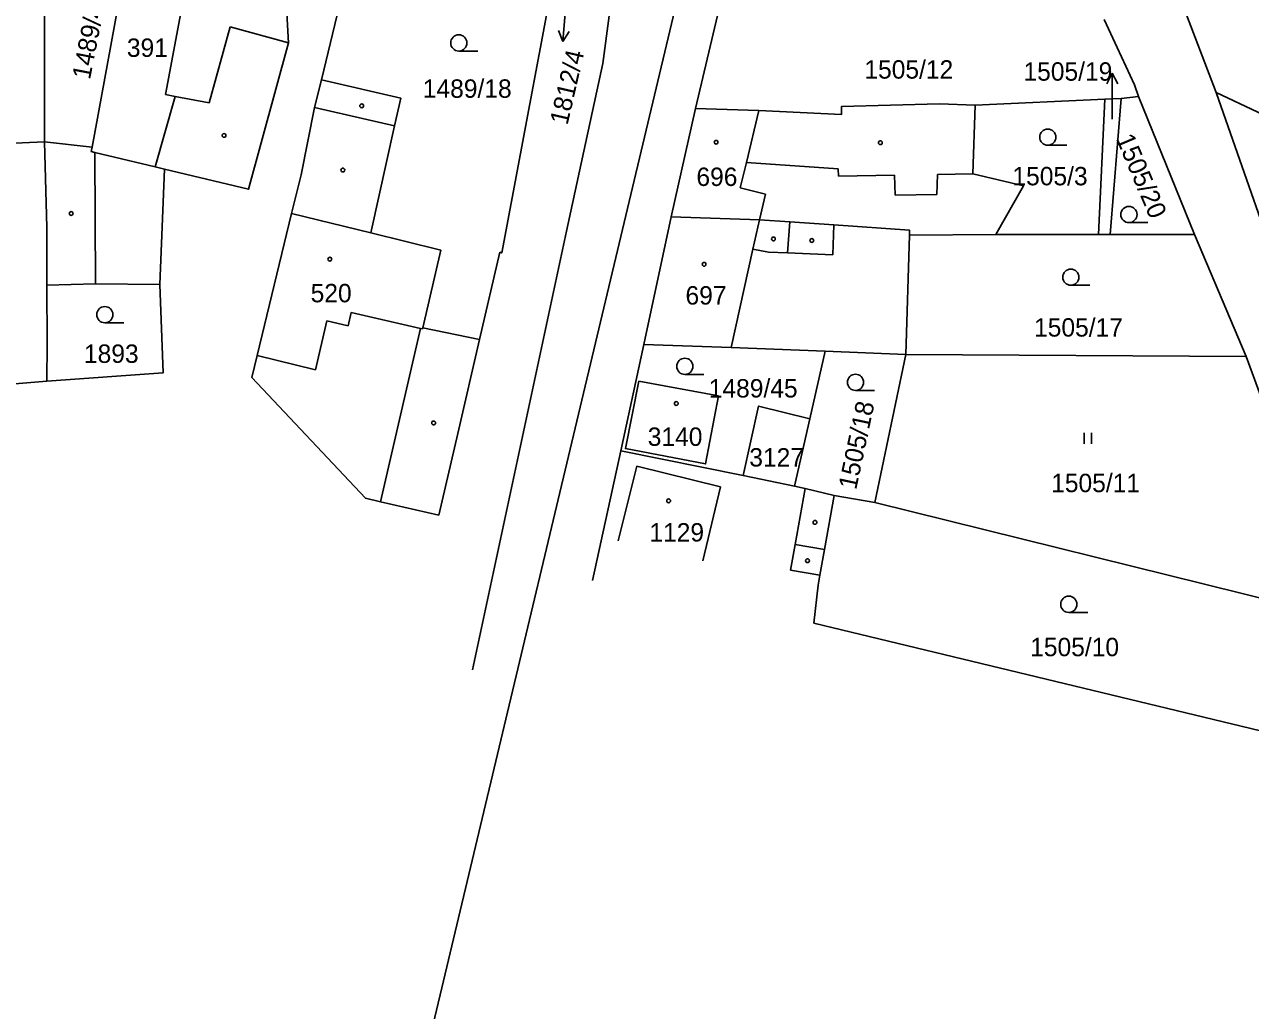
# Model space of a CAD drawing. Extents: x -779330 to -774454, y -1144748 to -1142831.
# Drawn here: x -777374.1 to -777260.7, y -1144037.5 to -1143946.4 of the extents above; entities that cross this region are included whole.
import ezdxf

# ---------------------------------------------------------------- set-up
doc = ezdxf.new("R2010")
doc.units = 0
for name, color, linetype in [('Hranice parcel', 7, 'Continuous'), ('Parcelní čísla', 7, 'Continuous'), ('Pop  PČ popisy', 7, 'Continuous'), ('Vnitřní kresba', 7, 'Continuous'), ('Značky budov', 7, 'Continuous'), ('Značky kultur', 7, 'Continuous')]:
    doc.layers.add(name, color=color, linetype=linetype)

msp = doc.modelspace()

# ---------------------------------------------------------------- linework, layer by layer
at = {"layer": 'Hranice parcel'}
for p, q in [((-777372.24, -1143957.25), (-777372.2, -1143931.77)), ((-777346.63, -1143951.52), (-777343.75, -1143939.71)), ((-777312.04, -1143954.18), (-777309.73, -1143944.43)), ((-777266.65, -1143945.51), (-777263.88, -1143952.69)), ((-777274.18, -1143953.33), (-777286.17, -1143953.86)), ((-777274.76, -1143965.81), (-777274.18, -1143953.33)), ((-777274.18, -1143953.33), (-777272.69, -1143953.26)), ((-777273.69, -1143965.81), (-777272.69, -1143953.26)), ((-777272.69, -1143953.26), (-777271.08, -1143953.07)), ((-777265.9, -1143965.83), (-777271.08, -1143953.07)), ((-777263.88, -1143952.69), (-777258.48, -1143968.19)), ((-777312.04, -1143954.18), (-777314.28, -1143964.19)), ((-777314.28, -1143964.19), (-777316.81, -1143975.99)), ((-777292.6, -1143976.92), (-777292.26, -1143965.88)), ((-777292.26, -1143965.88), (-777284.26, -1143965.84)), ((-777284.26, -1143965.84), (-777274.76, -1143965.81)), ((-777273.69, -1143965.81), (-777274.76, -1143965.81)), ((-777265.9, -1143965.83), (-777273.69, -1143965.81)), ((-777261.12, -1143977.11), (-777265.9, -1143965.83)), ((-777318.94, -1143985.81), (-777316.81, -1143975.99)), ((-777301.46, -1143982.86), (-777300.05, -1143976.62)), ((-777300.05, -1143976.62), (-777292.6, -1143976.92)), ((-777292.6, -1143976.92), (-777295.44, -1143990.58)), ((-777261.12, -1143977.11), (-777292.6, -1143976.92)), ((-777252.26, -1144001.3), (-777261.12, -1143977.11)), ((-777301.46, -1143982.86), (-777302.87, -1143989.08)), ((-777318.94, -1143985.81), (-777321.57, -1143997.81)), ((-777307.63, -1143988.11), (-777318.94, -1143985.81)), ((-777302.87, -1143989.08), (-777307.63, -1143988.11)), ((-777295.44, -1143990.58), (-777299.22, -1143989.94)), ((-777252.26, -1144001.3), (-777295.44, -1143990.58)), ((-777301.08, -1144001.76), (-777246.41, -1144014.94))]:
    msp.add_line(p, q, dxfattribs=at)
for points in [[(-777294.6, -1143849.93), (-777307.3, -1143865.67), (-777309.05, -1143868.8), (-777311.09, -1143883.18), (-777313.96, -1143945.06), (-777339.24, -1144051.23), (-777343.7, -1144063.85), (-777354.92, -1144095.57), (-777359.4, -1144105.13), (-777377.33, -1144140.81), (-777384.39, -1144152.73), (-777399.7, -1144183.35)], [(-777332.65, -1144006.07), (-777323.96, -1143965.53), (-777320.6, -1143950.03), (-777317.86, -1143929.35), (-777317.3, -1143892.87), (-777317.93, -1143883.67), (-777320.94, -1143881.7)], [(-777363.4, -1143933.71), (-777367.83, -1143957.76), (-777372.24, -1143957.25)], [(-777361.57, -1143970.44), (-777361.14, -1143959.78), (-777353.37, -1143961.64), (-777349.67, -1143948.11), (-777350.18, -1143938.72), (-777350.82, -1143936.44), (-777357.51, -1143934.99), (-777363.4, -1143933.71)], [(-777325.64, -1143944.56), (-777329.95, -1143967.52), (-777330.12, -1143967.47), (-777332.01, -1143975.52)], [(-777271.08, -1143953.07), (-777271.45, -1143951.98), (-777274.26, -1143945.97)], [(-777346.63, -1143951.52), (-777347.26, -1143954.09), (-777348.51, -1143960.32), (-777349.38, -1143963.89), (-777352.57, -1143977.01), (-777353.07, -1143979.04), (-777342.56, -1143990.2), (-777341.15, -1143990.53), (-777335.78, -1143991.75), (-777334.01, -1143984.21), (-777332.01, -1143975.52)], [(-777332.01, -1143975.52), (-777337.26, -1143974.45), (-777335.59, -1143967.26), (-777342.05, -1143965.68), (-777339.86, -1143955.79), (-777339.29, -1143953.22), (-777346.63, -1143951.52)], [(-777171.18, -1143997.24), (-777214.44, -1143976.01), (-777263.88, -1143952.69)], [(-777286.17, -1143953.86), (-777289.46, -1143953.75), (-777298.53, -1143953.99), (-777298.52, -1143954.72), (-777306.18, -1143954.38), (-777312.04, -1143954.18)], [(-777284.26, -1143965.84), (-777281.7, -1143961.34), (-777286.39, -1143960.23), (-777286.17, -1143953.86)], [(-777402.5, -1143958.01), (-777402.7, -1143965.53), (-777403.13, -1143981.77), (-777401.59, -1143981.77), (-777398.88, -1143981.65), (-777389.09, -1143980.8), (-777372.01, -1143979.38)], [(-777372.24, -1143957.25), (-777376.4, -1143957.46), (-777387.4, -1143958.06), (-777396.94, -1143957.77), (-777396.94, -1143958.12), (-777402.5, -1143958.01)], [(-777372.01, -1143970.52), (-777372, -1143965.18), (-777372.24, -1143957.25)], [(-777314.28, -1143964.19), (-777306.13, -1143964.46), (-777303.32, -1143964.66), (-777299.23, -1143964.94), (-777292.24, -1143965.43), (-777292.26, -1143965.88)], [(-777372.01, -1143970.52), (-777367.5, -1143970.39), (-777361.57, -1143970.44)], [(-777361.57, -1143970.44), (-777361.25, -1143978.6), (-777372.01, -1143979.38)], [(-777372.01, -1143979.38), (-777371.98, -1143975.94), (-777372.01, -1143970.52)], [(-777316.81, -1143975.99), (-777308.74, -1143976.27), (-777300.05, -1143976.62)], [(-777317.28, -1143979.37), (-777309.91, -1143980.75), (-777311.11, -1143987.03), (-777318.52, -1143985.61), (-777317.28, -1143979.37)], [(-777307.63, -1143988.11), (-777306.2, -1143981.69), (-777301.46, -1143982.86)], [(-777299.22, -1143989.94), (-777301.9, -1143989.31), (-777302.87, -1143989.08)], [(-777301.08, -1144001.76), (-777300.69, -1143998.22), (-777300.53, -1143997.32), (-777300.11, -1143994.95), (-777299.22, -1143989.94)]]:
    msp.add_lwpolyline(points, dxfattribs=at)
at = {"layer": 'Pop  PČ popisy'}
for p, q in [((-777324.04, -1143945.01), (-777324.3, -1143948)), ((-777324.3, -1143948), (-777324.71, -1143946.96)), ((-777324.3, -1143948), (-777323.71, -1143947.05)), ((-777273.5, -1143950.91), (-777274, -1143951.91)), ((-777273.5, -1143953.91), (-777273.5, -1143950.91)), ((-777273.5, -1143950.91), (-777273, -1143951.91)), ((-777273.5, -1143955.17), (-777273.5, -1143953.91))]:
    msp.add_line(p, q, dxfattribs=at)
at = {"layer": 'Vnitřní kresba'}
for p, q in [((-777361.03, -1143952.89), (-777358.8, -1143940.92)), ((-777355.07, -1143946.63), (-777357, -1143953.67)), ((-777355.07, -1143946.63), (-777349.67, -1143948.11)), ((-777360.15, -1143953.06), (-777361.99, -1143959.57)), ((-777361.03, -1143952.89), (-777360.15, -1143953.06)), ((-777360.15, -1143953.06), (-777357, -1143953.67)), ((-777347.26, -1143954.09), (-777339.86, -1143955.79)), ((-777307.32, -1143959.16), (-777306.18, -1143954.38)), ((-777367.83, -1143957.76), (-777367.9, -1143958.16)), ((-777367.9, -1143958.16), (-777367.56, -1143958.24)), ((-777367.56, -1143958.24), (-777361.99, -1143959.57)), ((-777367.5, -1143970.39), (-777367.56, -1143958.24)), ((-777307.9, -1143961.52), (-777307.32, -1143959.16)), ((-777307.32, -1143959.16), (-777298.83, -1143959.77)), ((-777361.99, -1143959.57), (-777361.14, -1143959.78)), ((-777298.83, -1143959.77), (-777298.81, -1143960.42)), ((-777298.81, -1143960.42), (-777293.64, -1143960.34)), ((-777293.64, -1143960.34), (-777293.58, -1143962.2)), ((-777289.73, -1143962.14), (-777289.65, -1143960.28)), ((-777289.65, -1143960.28), (-777286.39, -1143960.23)), ((-777305.55, -1143962.1), (-777307.9, -1143961.52)), ((-777306.13, -1143964.46), (-777305.55, -1143962.1)), ((-777293.58, -1143962.2), (-777289.73, -1143962.14)), ((-777349.38, -1143963.89), (-777342.05, -1143965.68)), ((-777306.74, -1143967.19), (-777306.13, -1143964.46)), ((-777303.32, -1143964.66), (-777303.54, -1143967.53)), ((-777299.34, -1143967.71), (-777299.23, -1143964.94)), ((-777308.74, -1143976.27), (-777306.74, -1143967.19)), ((-777306.74, -1143967.19), (-777305.28, -1143967.45)), ((-777305.28, -1143967.45), (-777303.54, -1143967.53)), ((-777303.54, -1143967.53), (-777299.34, -1143967.71)), ((-777347.17, -1143978.33), (-777346.12, -1143973.8)), ((-777346.12, -1143973.8), (-777344.16, -1143974.26)), ((-777344.16, -1143974.26), (-777343.87, -1143973.02)), ((-777343.87, -1143973.02), (-777337.46, -1143974.51)), ((-777341.15, -1143990.53), (-777337.46, -1143974.51)), ((-777337.46, -1143974.51), (-777337.28, -1143974.55)), ((-777337.28, -1143974.55), (-777337.26, -1143974.45)), ((-777352.57, -1143977.01), (-777347.17, -1143978.33)), ((-777319.18, -1143994.13), (-777317.45, -1143987.24)), ((-777317.45, -1143987.24), (-777309.72, -1143989.14)), ((-777309.72, -1143989.14), (-777311.35, -1143995.99)), ((-777301.9, -1143989.31), (-777302.83, -1143994.47)), ((-777303.25, -1143996.84), (-777302.83, -1143994.47)), ((-777302.83, -1143994.47), (-777300.11, -1143994.95)), ((-777300.53, -1143997.32), (-777303.25, -1143996.84))]:
    msp.add_line(p, q, dxfattribs=at)
at = {"layer": 'Značky budov'}
for centre in [(-777342.9, -1143953.93), (-777355.63, -1143956.67), (-777310.13, -1143957.3), (-777294.94, -1143957.34), (-777344.64, -1143959.87), (-777369.76, -1143963.88), (-777304.83, -1143966.24), (-777301.28, -1143966.38), (-777345.84, -1143968.1), (-777311.24, -1143968.58), (-777313.81, -1143981.44), (-777336.25, -1143983.24), (-777314.52, -1143990.44), (-777300.99, -1143992.43), (-777301.68, -1143995.97)]:
    msp.add_circle(centre, 0.175, dxfattribs=at)
at = {"layer": 'Značky kultur'}
for p, q in [((-777333.92, -1143948.87), (-777332.17, -1143948.87)), ((-777279.46, -1143957.58), (-777277.71, -1143957.58)), ((-777271.96, -1143964.73), (-777270.21, -1143964.73)), ((-777277.33, -1143970.52), (-777275.58, -1143970.52)), ((-777366.65, -1143973.98), (-777364.9, -1143973.98)), ((-777313.02, -1143978.76), (-777311.27, -1143978.76)), ((-777297.24, -1143980.24), (-777295.49, -1143980.24)), ((-777276.1, -1143985.16), (-777276.1, -1143984.16)), ((-777275.43, -1143985.16), (-777275.43, -1143984.16)), ((-777277.52, -1144000.75), (-777275.77, -1144000.75))]:
    msp.add_line(p, q, dxfattribs=at)
for centre in [(-777333.92, -1143948.12), (-777279.46, -1143956.83), (-777271.96, -1143963.98), (-777277.33, -1143969.77), (-777366.65, -1143973.23), (-777313.02, -1143978.01), (-777297.24, -1143979.49), (-777277.52, -1144000)]:
    msp.add_circle(centre, 0.75, dxfattribs=at)

# ---------------------------------------------------------------- texts
at = {"layer": 'Parcelní čísla'}
for s, rotation, p in [('1489/49', 79, (-777368.02, -1143951.57)), ('1812/4', 77, (-777323.87, -1143955.77)), ('1505/20', 293, (-777273.18, -1143956.94)), ('1505/18', 78, (-777297.18, -1143989.48))]:
    msp.add_text(s, height=1.7, rotation=rotation, dxfattribs=at).set_placement(p)
for s, p in [('391', (-777364.61, -1143949.41)), ('1505/12', (-777296.42, -1143951.42)), ('1505/19', (-777281.71, -1143951.61)), ('1489/18', (-777337.25, -1143953.19)), ('696', (-777311.95, -1143961.34)), ('1505/3', (-777282.73, -1143961.28)), ('520', (-777347.62, -1143972.09)), ('697', (-777312.96, -1143972.3)), ('1505/17', (-777280.73, -1143975.26)), ('1893', (-777368.58, -1143977.69)), ('1489/45', (-777310.81, -1143980.89)), ('3140', (-777316.45, -1143985.36)), ('3127', (-777307.06, -1143987.27)), ('1505/11', (-777279.15, -1143989.64)), ('1129', (-777316.3, -1143994.2)), ('1505/10', (-777281.09, -1144004.8))]:
    msp.add_text(s, height=1.7, dxfattribs=at).set_placement(p)

doc.saveas('drawing.dxf')
